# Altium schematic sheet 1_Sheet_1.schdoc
size 599 x 426 mm; Name: A_A2; Symbol: A_A2; Device: A_A2; @Project Name: HydromatMK1_2025-12-27_13-47-41; REV: 1.0; Date: 2025-12-12; Sheet: 1/1; Company: Your Company; Convert to PCB: yes; Add into BOM: yes; spicePre: .; @Page No: 1; @Page Count: 1; @Schematic Name: HydromatMK1; @Board Name: HydromatMK1; @Update Date: 2026-03-11; @Create Time: 13:47:52; @Update Time: 00:05:39; @Page Name: Sheet_1; @Create Date: 2025-12-27
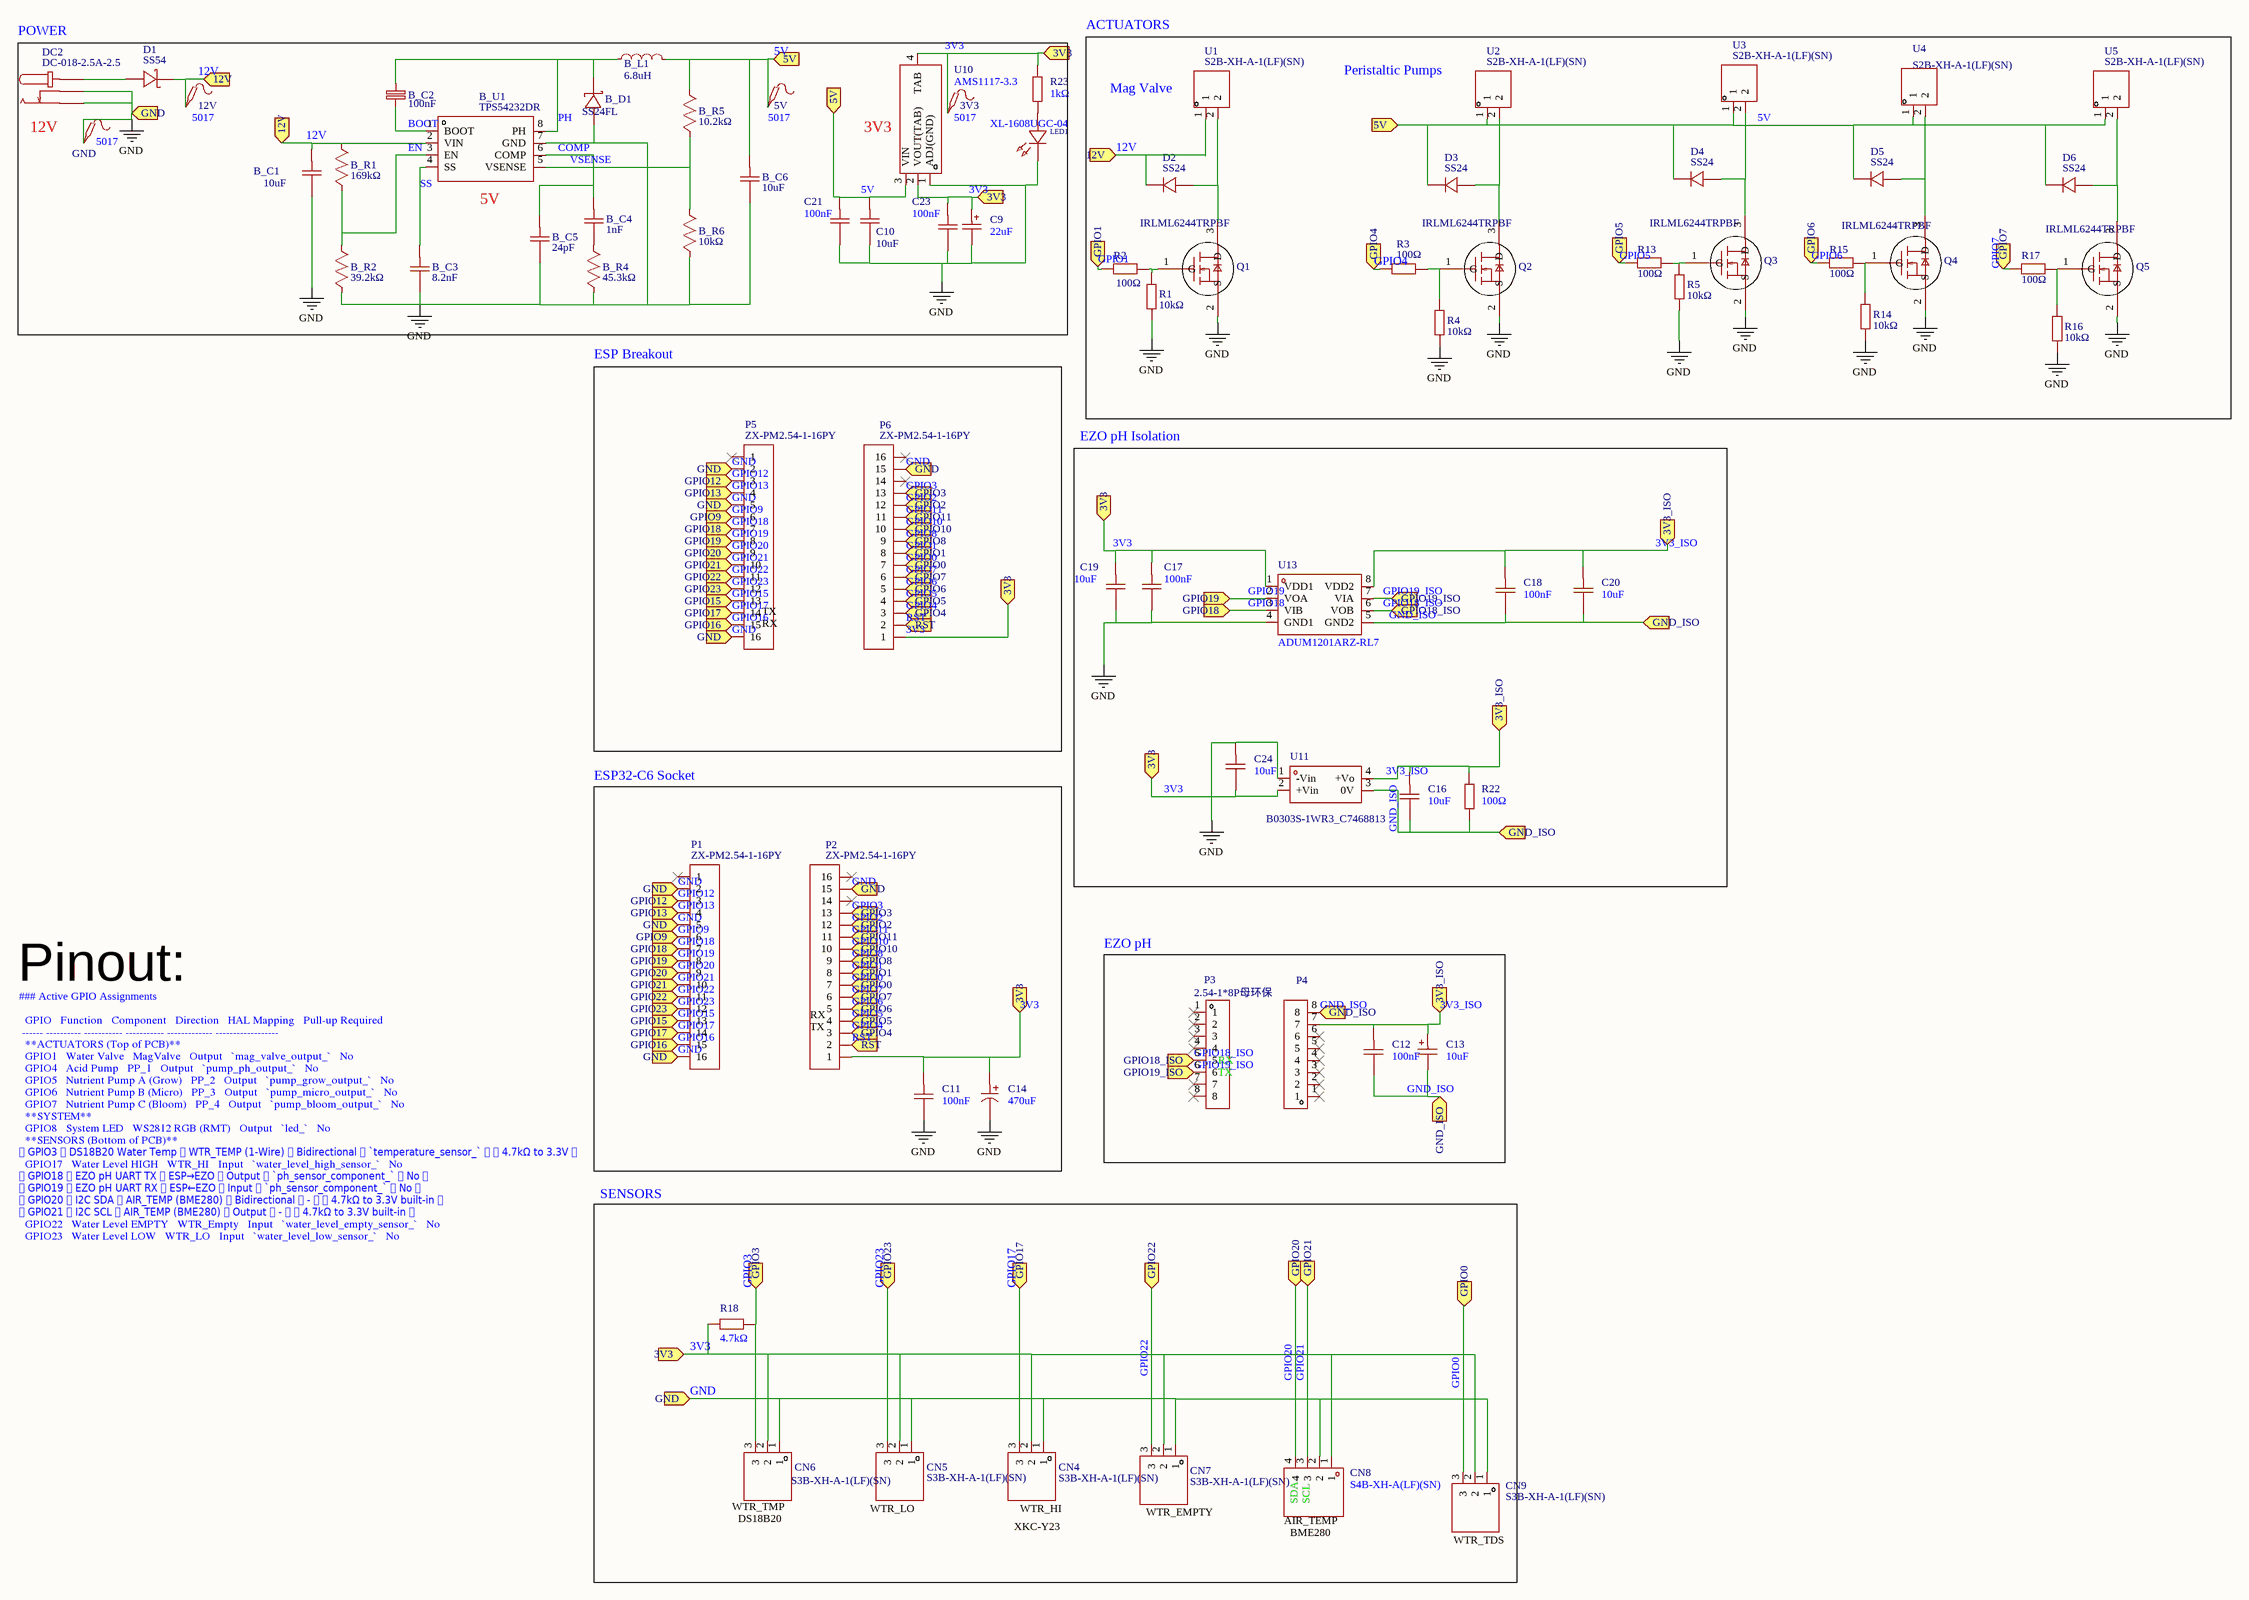
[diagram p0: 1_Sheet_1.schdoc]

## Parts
3V3  5017  [TEST-SMD_L2.7-W1.0]
5V  5017  [TEST-SMD_L2.7-W1.0]
12V  5017  [TEST-SMD_L2.7-W1.0]
B_C1  10uF  [C0603]
B_C2  100nF  [C0603]
B_C3  8.2nF  [C0805]
B_C4  1nF  [C0805]
B_C5  24pF  [C0805]
B_C6  10uF  [C0805]
B_D1  SS24FL  [SOD-123_L2.6-W1.6-LS3.5-RD]
B_L1  6.8uH  [IND-SMD_L2.5-W2.0_FTC252010S]
B_R1  169kΩ  [R0603]
B_R2  39.2kΩ  [R0603]
B_R4  45.3kΩ  [R0805]
B_R5  10.2kΩ  [R0805]
B_R6  10kΩ  [R0805]
B_U1  TPS54232DR  [SOIC-8_L4.9-W3.9-P1.27-LS6.0-BL]
C9  22uF  [CASE-B_3528]
C10  10uF  [C0805]
C11  100nF  [C0805]
C12  100nF  [C0805]
C13  10uF  [CAP-SMD_L3.2-W1.6-RD-C7171]
C14  470uF  [CAP-SMD_BD10.0-L10.3-W10.3-LS11.0-FD]
C16  10uF  [C0805]
C17  100nF  [C0805]
C18  100nF  [C0805]
C19  10uF  [C0805]
C20  10uF  [C0805]
C21  100nF  [C0805]
C23  100nF  [C0805]
C24  10uF  [C0805]
CN4  S3B-XH-A-1(LF)(SN)  [CONN-TH_S3B-XH-A-1-LF-SN]
CN5  S3B-XH-A-1(LF)(SN)  [CONN-TH_S3B-XH-A-1-LF-SN]
CN6  S3B-XH-A-1(LF)(SN)  [CONN-TH_S3B-XH-A-1-LF-SN]
CN7  S3B-XH-A-1(LF)(SN)  [CONN-TH_S3B-XH-A-1-LF-SN]
CN8  S4B-XH-A(LF)(SN)  [CONN-TH_S4B-XH-A-LF-SN]
CN9  S3B-XH-A-1(LF)(SN)  [CONN-TH_S3B-XH-A-1-LF-SN]
D1  SS54  [SMA_L4.3-W2.6-LS5.1-RD]
D2  SS24  [SMA_L4.3-W2.6-LS5.0-FD]
D3  SS24  [SMA_L4.3-W2.6-LS5.0-FD]
D4  SS24  [SMA_L4.3-W2.6-LS5.0-FD]
D5  SS24  [SMA_L4.3-W2.6-LS5.0-FD]
D6  SS24  [SMA_L4.3-W2.6-LS5.0-FD]
DC2  DC-018-2.5A-2.5  [DC-IN-TH_DC-018]
GND  5017  [TEST-SMD_L2.7-W1.0]
LED1  XL-1608UGC-04  [LED0603-RD_GREEN]
P1  ZX-PM2.54-1-16PY  [HDR-TH_16P-P2.54-V-F-1]
P2  ZX-PM2.54-1-16PY  [HDR-TH_16P-P2.54-V-F-1]
P3  2.54-1*8P母环保  [HDR-TH_8P-P2.54-V-F_2]
P4  2.54-1*8P母环保  [HDR-TH_8P-P2.54-V-F_2]  (value not drawn)
P5  ZX-PM2.54-1-16PY  [HDR-TH_16P-P2.54-V-F-1]
P6  ZX-PM2.54-1-16PY  [HDR-TH_16P-P2.54-V-F-1]
Q1  IRLML6244TRPBF  [SOT-23-3_L2.9-W1.3-P1.90-LS2.4-BR]
Q2  IRLML6244TRPBF  [SOT-23-3_L2.9-W1.3-P1.90-LS2.4-BR]
Q3  IRLML6244TRPBF  [SOT-23-3_L2.9-W1.3-P1.90-LS2.4-BR]
Q4  IRLML6244TRPBF  [SOT-23-3_L2.9-W1.3-P1.90-LS2.4-BR]
Q5  IRLML6244TRPBF  [SOT-23-3_L2.9-W1.3-P1.90-LS2.4-BR]
R1  10kΩ  [R0805]
R2  100Ω  [R0805]
R3  100Ω  [R0805]
R4  10kΩ  [R0805]
R5  10kΩ  [R0805]
R13  100Ω  [R0805]
R14  10kΩ  [R0805]
R15  100Ω  [R0805]
R16  10kΩ  [R0805]
R17  100Ω  [R0805]
R18  4.7kΩ  [R0805]
R22  100Ω  [R0805]
R23  1kΩ  [R0805]
U1  S2B-XH-A-1(LF)(SN)  [CONN-TH_S2B-XH-A-1-LF-SN]
U2  S2B-XH-A-1(LF)(SN)  [CONN-TH_S2B-XH-A-1-LF-SN]
U3  S2B-XH-A-1(LF)(SN)  [CONN-TH_S2B-XH-A-1-LF-SN]
U4  S2B-XH-A-1(LF)(SN)  [CONN-TH_S2B-XH-A-1-LF-SN]
U5  S2B-XH-A-1(LF)(SN)  [CONN-TH_S2B-XH-A-1-LF-SN]
U10  AMS1117-3.3  [SOT-223-4_L6.5-W3.5-P2.30-LS7.0-BR]
U11  220kHz  [PWRM-TH_B0303S-1WR3]  (value not drawn)
U13  ADUM1201ARZ-RL7  [SOIC-8_L4.9-W3.9-P1.27-LS6.0-BL]

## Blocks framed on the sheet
ESP Breakout: P5 P6
EZO pH Isolation: C16-C20 C24 R22 U11 U13
ESP32-C6 Socket: C11 C14 P1 P2
EZO pH: C12 C13 P3 P4
SENSORS: CN4-CN9 R18

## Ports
3V3 (in), 3V3_ISO (in), 5V (in), 12V (in), GND (in), GND_ISO (in), GPIO0 (in), GPIO1 (in), GPIO2 (in), GPIO3 (in), GPIO4 (in), GPIO5 (in), GPIO6 (in), GPIO7 (in), GPIO8 (in), GPIO9 (in), GPIO10 (in), GPIO11 (in), GPIO12 (in), GPIO13 (in), GPIO15 (in), GPIO16 (in), GPIO17 (in), GPIO18 (in), GPIO18_ISO (in), GPIO19 (in), GPIO19_ISO (in), GPIO20 (in), GPIO21 (in), GPIO22 (in), GPIO23 (in), RST (in)

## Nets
GND: B_C1.1 B_C3.1 B_C5.1 B_C6.1 B_D1.2(A) B_R2.1 B_R4.1 B_R6.1 B_U1.7(GND) C9.2 C10.1 C11.1 C14.2 C17.1 C19.1 C21.1 C23.1 C24.2 CN4.1 CN5.1 CN6.1 CN7.1 CN8.2 CN9.1 DC2.2 DC2.3 GND.1 LED1.1(K) P1.2 P1.5 P1.16 P2.15 P5.2 P5.5 P5.16 P6.15 Q1.2(S) Q2.2(S) Q3.2(S) Q4.2(S) Q5.2(S) R1.1 R4.1 R5.1 R14.1 R16.1 U10.1(ADJ(GND)) U11.1(-Vin) U13.4(GND1) ; port GND
3V3: 3V3.1 C9.1 C11.2 C14.1 C17.2 C19.2 C23.2 C24.1 CN4.2 CN5.2 CN6.2 CN7.2 CN8.1 CN9.2 P2.1 P6.1 R18.1 R23.2 U10.2(VOUT(TAB)) U10.4(TAB) U11.2(+Vin) U13.1(VDD1) ; port 3V3
3V3_ISO: C12.2 C13.1 C16.2 C18.2 C20.2 P4.7 R22.2 U11.4(+Vo) U13.8(VDD2) ; port 3V3_ISO
5V: 5V.1 B_C6.2 B_L1.2 B_R5.2 C10.2 C21.2 D3.1(C) D4.1(C) D5.1(C) D6.1(C) U2.1 U3.1 U4.1 U5.1 U10.3(VIN) ; port 5V
12V: 12V.1 B_C1.2 B_R1.2 B_U1.2(VIN) D1.1(K) D2.1(C) U1.1 ; port 12V
BOOT: B_C2.2 B_U1.1(BOOT)
COMP: B_C4.2 B_C5.2 B_U1.6(COMP)
EN: B_R1.1 B_R2.2 B_U1.3(EN)
GND_ISO: C12.1 C13.2 C16.1 C18.1 C20.1 P4.8 R22.1 U11.3(0V) U13.5(GND2) ; port GND_ISO
GPIO0: CN9.3 P2.7 P6.7 ; port GPIO0
GPIO1: P2.8 P6.8 R2.1 ; port GPIO1
GPIO2: P2.12 P6.12 ; port GPIO2
GPIO3: CN6.3 P2.13 P6.13 R18.2 ; port GPIO3
GPIO4: P2.3 P6.3 R3.2 ; port GPIO4
GPIO5: P2.4 P6.4 R13.2 ; port GPIO5
GPIO6: P2.5 P6.5 R15.2 ; port GPIO6
GPIO7: P2.6 P6.6 R17.1 ; port GPIO7
GPIO8: P2.9 P6.9 ; port GPIO8
GPIO9: P1.6 P5.6 ; port GPIO9
GPIO10: P2.10 P6.10 ; port GPIO10
GPIO11: P2.11 P6.11 ; port GPIO11
GPIO12: P1.3 P5.3 ; port GPIO12
GPIO13: P1.4 P5.4 ; port GPIO13
GPIO15: P1.13 P5.13 ; port GPIO15
GPIO16: P1.15 P5.15 ; port GPIO16
GPIO17: CN4.3 P1.14 P5.14 ; port GPIO17
GPIO18: P1.7 P5.7 U13.3(VIB) ; port GPIO18
GPIO18_ISO: P3.5 U13.6(VOB) ; port GPIO18_ISO
GPIO19: P1.8 P5.8 U13.2(VOA) ; port GPIO19
GPIO19_ISO: P3.6 U13.7(VIA) ; port GPIO19_ISO
GPIO20: CN8.4 P1.9 P5.9 ; port GPIO20
GPIO21: CN8.3 P1.10 P5.10 ; port GPIO21
GPIO22: CN7.3 P1.11 P5.11 ; port GPIO22
GPIO23: CN5.3 P1.12 P5.12 ; port GPIO23
PH: B_C2.1 B_D1.1(K) B_L1.1 B_U1.8(PH)
RST: P2.2 P6.2 ; port RST
SS: B_C3.2 B_U1.4(SS)
VSENSE: B_R5.1 B_R6.2 B_U1.5(VSENSE)
NetB_C4_1: B_C4.1 B_R4.2
NetD1_2: D1.2(A) DC2.1
NetD2_2: D2.2(A) Q1.3(D) U1.2
NetD3_2: D3.2(A) Q2.3(D) U2.2
NetD4_2: D4.2(A) Q3.3(D) U3.2
NetD5_2: D5.2(A) Q4.3(D) U4.2
NetD6_2: D6.2(A) Q5.3(D) U5.2
NetLED1_2: LED1.2(A) R23.1
NetQ1_1: Q1.1(G) R1.2 R2.2
NetQ2_1: Q2.1(G) R3.1 R4.2
NetQ3_1: Q3.1(G) R5.2 R13.1
NetQ4_1: Q4.1(G) R14.2 R15.1
NetQ5_1: Q5.1(G) R16.2 R17.2

Not connected (* = marked no-connect by the designer): P1 1*; P2 14* 16*; P3 1* 2* 3* 4* 7* 8*; P4 1* 2* 3* 4* 5* 6*; P5 1*; P6 14* 16*

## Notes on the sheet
- (near DC2) POWER
- ACTUATORS
- (near U1) Mag Valve
- (near U2) Peristaltic Pumps
- (near DC2) 12V
- (near U10) 3V3
- (near B_U1) 5V
- (near P5) TX
- (near P5) RX
- Pinout:
- ### Active GPIO Assignments
   GPIO  Function  Component  Direction  HAL Mapping  Pull-up Required 
  ---------------------------------------------------------------------
   **ACTUATORS (Top of PCB)** 
   GPIO1  Water Valve  MagValve  Output  `mag_valve_output_`  No 
   GPIO4  Acid Pump  PP_1  Output  `pump_ph_output_`  No 
   GPIO5  Nutrient Pump A (Grow)  PP_2  Output  `pump_grow_output_`  No 
   GPIO6  Nutrient Pump B (Micro)  PP_3  Output  `pump_micro_output_`  No 
   GPIO7  Nutrient Pump C (Bloom)  PP_4  Output  `pump_bloom_output_`  No 
   **SYSTEM** 
   GPIO8  System LED  WS2812 RGB (RMT)  Output  `led_`  No 
   **SENSORS (Bottom of PCB)** 
   GPIO3  DS18B20 Water Temp  WTR_TEMP (1-Wire)  Bidirectional  `temperature_sensor_`  ✅ 4.7kΩ to 3.3V 
   GPIO17  Water Level HIGH  WTR_HI  Input  `water_level_high_sensor_`  No 
   GPIO18  EZO pH UART TX  ESP→EZO  Output  `ph_sensor_component_`  No 
   GPIO19  EZO pH UART RX  ESP←EZO  Input  `ph_sensor_component_`  No 
   GPIO20  I2C SDA  AIR_TEMP (BME280)  Bidirectional  -  ✅ 4.7kΩ to 3.3V built-in 
   GPIO21  I2C SCL  AIR_TEMP (BME280)  Output  -  ✅ 4.7kΩ to 3.3V built-in 
   GPIO22  Water Level EMPTY  WTR_Empty  Input  `water_level_empty_sensor_`  No 
   GPIO23  Water Level LOW  WTR_LO  Input  `water_level_low_sensor_`  No 
- (near P2) TX
- (near P2) RX
- (near P3) RX
- (near P3) TX
- WTR_TMP
- DS18B20
- WTR_LO
- XKC-Y23
- WTR_HI
- WTR_EMPTY
- AIR_TEMP
- BME280
- (near CN8) SDA
- (near CN8) SCL
- WTR_TDS

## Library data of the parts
3V3 = 5017_C238130: Manufacturer: Keystone; Symbol: Test-Point; Add into BOM: yes; Connector Type: Ferrite Ring (SMD); Plastic Color: Non-Plastic; Board Space (Diameter φ/ Length x Width): 3.4mmx1.8mm; Channel ID: $1e5103
5V = 5017_C238130: Manufacturer: Keystone; Symbol: Test-Point; Add into BOM: yes; Connector Type: Ferrite Ring (SMD); Plastic Color: Non-Plastic; Board Space (Diameter φ/ Length x Width): 3.4mmx1.8mm; Channel ID: $1e5005
12V = 5017_C238130: Manufacturer: Keystone; Symbol: Test-Point; Add into BOM: yes; Connector Type: Ferrite Ring (SMD); Plastic Color: Non-Plastic; Board Space (Diameter φ/ Length x Width): 3.4mmx1.8mm; Channel ID: $1e5056
B_C1 = CL10A106MO8NQNC: Manufacturer: SAMSUNG(三星); Add into BOM: yes; Tolerance: ±20%; Voltage Rating: 16V; Temperature Coefficient: X5R; Channel ID: $1e1201
B_C2 = CC0603KRX7R9BB104: Manufacturer: YAGEO(国巨); Add into BOM: yes; Tolerance: ±10%; Voltage Rating: 50V; Temperature Coefficient: X7R; Origin Footprint: C0402; Channel ID: $1e1005
B_C3 = CC0805JRX7R9BB822: Manufacturer: YAGEO(国巨); Add into BOM: yes; Tolerance: ±5%; Voltage Rating: 50V; Temperature Coefficient: X7R; Origin Footprint: C0201; nameAlias: Value(F); Contributor: LCEDA_Lib; Channel ID: $1e1053
B_C4 = CL21B102KBCNNNC: Manufacturer: SAMSUNG(三星); Add into BOM: yes; Tolerance: ±10%; Voltage Rating: 50V; Temperature Coefficient: X7R; Channel ID: $1e1165
B_C5 = 0805CG240J500NT: Manufacturer: FH(风华); Add into BOM: yes; Tolerance: ±5%; Voltage Rating: 50V; Temperature Coefficient: C0G; Channel ID: $1e1147
B_C6 = CL21A106KBYQNNE: Manufacturer: SAMSUNG(三星); Add into BOM: yes; Tolerance: ±10%; Voltage Rating: 50V; Temperature Coefficient: X5R; Origin Footprint: C1206; nameAlias: Value(F); Contributor: LCEDA_Lib; Channel ID: $1e1093
B_D1 = SS24FL: Manufacturer: KEXIN(科信); Symbol: SS24FL_C489144; Add into BOM: yes; Voltage - Forward(Vf@If): 550mV@2A; Voltage - DC Reverse(Vr): 40V; Current - Rectified: 2A; Non-Repetitive Peak Forward Surge Current: 50A; Contributor: LCSC; Channel ID: $1e1222
B_L1 = FTC252012S6R8MBCA: Manufacturer: cjiang(长江微电); Add into BOM: yes; Tolerance: ±20%; Current Rating: 1.6A; Current - Saturation(Isat): 2A; DC Resistance(DCR): 245mΩ; Origin Footprint: L0805; nameAlias: Value(H); Contributor: LCEDA_Lib; Channel ID: $1e1075
B_R1 = 0603WAF1693T5E: Manufacturer: UNI-ROYAL(厚声); Symbol: 169K; Add into BOM: yes; Tolerance: ±1%; Temperature Coefficient: ±100ppm/℃; Origin Footprint: R0402; nameAlias: Value(Ω); Contributor: LCEDA_Lib; Channel ID: $1e1017; Voltage-Supply(Max): 50V
B_R2 = 0603WAF3922T5E: Manufacturer: UNI-ROYAL(厚声); Symbol: 39K2; Add into BOM: yes; Tolerance: ±1%; Power(Watts): 100mW; Voltage-Supply(Max): 75V; Temperature Coefficient: ±100ppm/℃; Origin Footprint: R0402; nameAlias: Value(Ω); Contributor: LCEDA_Lib; Channel ID: $1e1035
B_R4 = FRC0805F4532TS: Manufacturer: FOJAN(富捷); Symbol: 45K3; Add into BOM: yes; Tolerance: ±1%; Power(Watts): 125mW; Voltage-Supply(Max): 150V; Temperature Coefficient: ±100ppm/℃; Origin Footprint: R0402; nameAlias: Value(Ω); Contributor: LCEDA_Lib; Channel ID: $1e1183
B_R5 = FRC0805F1022TS: Manufacturer: FOJAN(富捷); Symbol: 10K2; Add into BOM: yes; Tolerance: ±1%; Power(Watts): 125mW; Voltage-Supply(Max): 150V; Temperature Coefficient: ±100ppm/℃; Origin Footprint: R0402; nameAlias: Value(Ω); Contributor: LCEDA_Lib; Channel ID: $1e1111
B_R6 = FRC0805J103TS: Manufacturer: FOJAN(富捷); Symbol: 1K87; Add into BOM: yes; Tolerance: ±5%; Power(Watts): 125mW; Voltage-Supply(Max): 150V; Temperature Coefficient: ±100ppm/℃; Channel ID: $1e1129
B_U1 = TPS54232DR: Manufacturer: TI(德州仪器); Add into BOM: yes; Function: Step-down type; Output Type: Adjustable; Input Voltage: 3.5V~28V; Output Voltage: 800mV~28V; Output Current: 2A; Switching Frequency: 1MHz; Synchronous Rectification: No; Number of Outputs: 1; Topology: Step-down; Switch tube (built-in/external): Built-in; Contributor: LCSC; Channel ID: $1e983
C9 = TAJB226K016RNJ: Manufacturer: Kyocera AVX; Add into BOM: yes; Tolerance: ±10%; Voltage Rating: 16V; Equivalent Series Resistance(ESR): 2.3Ω@100kHz
C10 = 10uF: Manufacturer Part: CL21A106KAYNNNE; Manufacturer: SAMSUNG(三星); Convert to PCB: yes; nameAlias: Value
C11 = CC0805KRX7R9BB104: Manufacturer: YAGEO(国巨); Symbol: CC0603KRX7R9BB104; Add into BOM: yes; Tolerance: ±10%; Voltage Rating: 50V; Temperature Coefficient: X7R; Channel ID: $1e4020
C12 = CC0805KRX7R9BB104: Manufacturer: YAGEO(国巨); Symbol: CC0603KRX7R9BB104; Add into BOM: yes; Tolerance: ±10%; Voltage Rating: 50V; Temperature Coefficient: X7R; Channel ID: $1e4054
C13 = TAJA106K016RNJ: Manufacturer: Kyocera AVX; Add into BOM: yes; Tolerance: ±10%; Voltage Rating: 16V; Equivalent Series Resistance(ESR): 3Ω@100kHz
C14 = RVT1E471M1010: Manufacturer: HONOR(荣誉); Symbol: RVT1C471M0607; Add into BOM: yes; Tolerance: ±20%; Lifetime @ Temp: 2000hrs@105℃; Voltage Rating: 35V; Channel ID: $1e4226
C16 C19 C20 C24 = GRM21BR71A106KE51L: Manufacturer: muRata(村田); Add into BOM: yes; Tolerance: ±10%
C17 = CC0805KRX7R9BB104: Manufacturer: YAGEO(国巨); Symbol: CC0603KRX7R9BB104; Add into BOM: yes; Tolerance: ±10%; Voltage Rating: 50V; Temperature Coefficient: X7R; Channel ID: $1e8929
C18 = CC0805KRX7R9BB104: Manufacturer: YAGEO(国巨); Symbol: CC0603KRX7R9BB104; Add into BOM: yes; Tolerance: ±10%; Voltage Rating: 50V; Temperature Coefficient: X7R; Channel ID: $1e8963
C21 = CC0805KRX7R9BB104: Manufacturer: YAGEO(国巨); Symbol: CC0603KRX7R9BB104; Add into BOM: yes; Tolerance: ±10%; Voltage Rating: 50V; Temperature Coefficient: X7R; Channel ID: $1e12932
C23 = CC0805KRX7R9BB104: Manufacturer: YAGEO(国巨); Symbol: CC0603KRX7R9BB104; Add into BOM: yes; Tolerance: ±10%; Voltage Rating: 50V; Temperature Coefficient: X7R; Channel ID: $1e13045
CN4 = S3B-XH-A-1(LF)(SN): Manufacturer: JST; Symbol: S3B-XH-A (LF)(SN); Add into BOM: yes; Pins Structure: 1x3P; Pitch: 2.5mm; Reference Series: XH; Number of PINs Per Row: 3; Current Rating: 3A; Voltage Rating: 250V; Plastic Material: PA66; Flame Retardant Rating: UL94V-0; Supplementary Features: K Pin; Z-Height of the Board: 6.1mm; X-Length of Bottom Edge on Board (Spacing Line): 9.9mm; Y-Width of Bottom Edge on Board: 11.5mm; Origin Footprint: CONN-TH_S3B-XH-A-LF-SN; Contributor: LCSC; Channel ID: $1e1415
CN5 = S3B-XH-A-1(LF)(SN): Manufacturer: JST; Symbol: S3B-XH-A (LF)(SN); Add into BOM: yes; Pins Structure: 1x3P; Pitch: 2.5mm; Reference Series: XH; Number of PINs Per Row: 3; Current Rating: 3A; Voltage Rating: 250V; Plastic Material: PA66; Flame Retardant Rating: UL94V-0; Supplementary Features: K Pin; Z-Height of the Board: 6.1mm; X-Length of Bottom Edge on Board (Spacing Line): 9.9mm; Y-Width of Bottom Edge on Board: 11.5mm; Origin Footprint: CONN-TH_S3B-XH-A-LF-SN; Contributor: LCSC; Channel ID: $1e1433
CN6 = S3B-XH-A-1(LF)(SN): Manufacturer: JST; Symbol: S3B-XH-A (LF)(SN); Add into BOM: yes; Pins Structure: 1x3P; Pitch: 2.5mm; Reference Series: XH; Number of PINs Per Row: 3; Current Rating: 3A; Voltage Rating: 250V; Plastic Material: PA66; Flame Retardant Rating: UL94V-0; Supplementary Features: K Pin; Z-Height of the Board: 6.1mm; X-Length of Bottom Edge on Board (Spacing Line): 9.9mm; Y-Width of Bottom Edge on Board: 11.5mm; Origin Footprint: CONN-TH_S3B-XH-A-LF-SN; Contributor: LCSC; Channel ID: $1e1451
CN7 CN9 = S3B-XH-A-1(LF)(SN): Manufacturer: JST; Symbol: S3B-XH-A (LF)(SN); Add into BOM: yes; Pins Structure: 1x3P; Pitch: 2.5mm; Reference Series: XH; Number of PINs Per Row: 3; Current Rating: 3A; Voltage Rating: 250V; Plastic Material: PA66; Flame Retardant Rating: UL94V-0; Supplementary Features: K Pin; Z-Height of the Board: 6.1mm; X-Length of Bottom Edge on Board (Spacing Line): 9.9mm; Y-Width of Bottom Edge on Board: 11.5mm; Origin Footprint: CONN-TH_S3B-XH-A-LF-SN; Contributor: LCSC; Channel ID: $1e3939
CN8 = S4B-XH-A(LF)(SN): Manufacturer: JST; Add into BOM: yes; Pins Structure: 1x4P; Pitch: 2.5mm; Reference Series: XH; Number of PINs Per Row: 4; Current Rating: 3A; Voltage Rating: 250V; Plastic Material: PA66; Flame Retardant Rating: UL94V-0; Supplementary Features: K Pin; Z-Height of the Board: 6.1mm; X-Length of Bottom Edge on Board (Spacing Line): 12.4mm; Y-Width of Bottom Edge on Board: 11.5mm
D1 = SS54_C20609300: Manufacturer: JSMSEMI(杰盛微); Symbol: MBRS140T3G; Add into BOM: yes; Voltage - Forward(Vf@If): 550mV@5A; Voltage - DC Reverse(Vr): 40V; Current - Rectified: 5A; Reverse Leakage Current (Ir): 100uA@40V; Operating Junction Temperature Range: -55℃~+150℃; Non-Repetitive Peak Forward Surge Current: 100A; Origin Footprint: SMB_L4.6-W3.6-LS5.3-RD; Contributor: LCSC; Channel ID: $1e156
D2 = SS24_C7420362: Manufacturer: R+O(宏嘉诚); Symbol: 1N4148W-7-F; Add into BOM: yes; Diode Configuration: Independent; Voltage - Forward(Vf@If): 550mV@2A; Voltage - DC Reverse(Vr): 40V; Current - Rectified: 2A; Reverse Leakage Current (Ir): 200uA@40V; Operating Junction Temperature Range: -55℃~+150℃; Non-Repetitive Peak Forward Surge Current: 50A; Origin Footprint: SOD-123_L2.7-W1.6-LS3.7-RD-1; Channel ID: $1e228
D3 = SS24_C7420362: Manufacturer: R+O(宏嘉诚); Symbol: 1N4148W-7-F; Add into BOM: yes; Diode Configuration: Independent; Voltage - Forward(Vf@If): 550mV@2A; Voltage - DC Reverse(Vr): 40V; Current - Rectified: 2A; Reverse Leakage Current (Ir): 200uA@40V; Operating Junction Temperature Range: -55℃~+150℃; Non-Repetitive Peak Forward Surge Current: 50A; Origin Footprint: SOD-123_L2.7-W1.6-LS3.7-RD-1; Channel ID: $1e611
D4 = SS24_C7420362: Manufacturer: R+O(宏嘉诚); Symbol: 1N4148W-7-F; Add into BOM: yes; Diode Configuration: Independent; Voltage - Forward(Vf@If): 550mV@2A; Voltage - DC Reverse(Vr): 40V; Current - Rectified: 2A; Reverse Leakage Current (Ir): 200uA@40V; Operating Junction Temperature Range: -55℃~+150℃; Non-Repetitive Peak Forward Surge Current: 50A; Origin Footprint: SOD-123_L2.7-W1.6-LS3.7-RD-1; Channel ID: $1e736
D5 = SS24_C7420362: Manufacturer: R+O(宏嘉诚); Symbol: 1N4148W-7-F; Add into BOM: yes; Diode Configuration: Independent; Voltage - Forward(Vf@If): 550mV@2A; Voltage - DC Reverse(Vr): 40V; Current - Rectified: 2A; Reverse Leakage Current (Ir): 200uA@40V; Operating Junction Temperature Range: -55℃~+150℃; Non-Repetitive Peak Forward Surge Current: 50A; Origin Footprint: SOD-123_L2.7-W1.6-LS3.7-RD-1; Channel ID: $1e833
D6 = SS24_C7420362: Manufacturer: R+O(宏嘉诚); Symbol: 1N4148W-7-F; Add into BOM: yes; Diode Configuration: Independent; Voltage - Forward(Vf@If): 550mV@2A; Voltage - DC Reverse(Vr): 40V; Current - Rectified: 2A; Reverse Leakage Current (Ir): 200uA@40V; Operating Junction Temperature Range: -55℃~+150℃; Non-Repetitive Peak Forward Surge Current: 50A; Origin Footprint: SOD-123_L2.7-W1.6-LS3.7-RD-1; Channel ID: $1e930
DC2 = DC-018-2.5A-2.5: Manufacturer: XKB Connection(中国星坤); Convert to PCB: yes; Contributor: lcsc
GND = 5017_C238130: Manufacturer: Keystone; Symbol: Test-Point; Add into BOM: yes; Connector Type: Ferrite Ring (SMD); Plastic Color: Non-Plastic; Board Space (Diameter φ/ Length x Width): 3.4mmx1.8mm; Channel ID: $1e6615
LED1 = XL-1608UGC-04: Manufacturer: XINGLIGHT(成兴光); Add into BOM: yes; Illumination Color: Emerald Green; Voltage - Forward(Vf): 3.3V; Power(Watts): 70mW; Forward Current: 20mA; Wavelength - Dominant: 515nm~535nm; Peak Wavelength: 525nm; Diode Configuration: Discrete Diode; Lens Color: Water Clear; Luminous Intensity: 810mcd; Viewing Angle: 120°
P1 = ZX-PM2.54-1-16PY: Manufacturer: Megastar(兆星); Symbol: Header-Female-2.54_1x16; Add into BOM: yes; Holes Structure: 1x16P; Pitch: 2.54mm; Circular Hole / Square Hole: Square Hole; Number of Positions: 16P; Current Rating: 3A; Holes Direction: Top; PIN Length: 3.2mm; Channel ID: $1e329
P2 = ZX-PM2.54-1-16PY: Manufacturer: Megastar(兆星); Symbol: Header-Female-2.54_1x16; Add into BOM: yes; Holes Structure: 1x16P; Pitch: 2.54mm; Circular Hole / Square Hole: Square Hole; Number of Positions: 16P; Current Rating: 3A; Holes Direction: Top; PIN Length: 3.2mm; Channel ID: $1e105
P3 = 2.54-1*8P母环保: Manufacturer: BOOMELE(博穆精密); Symbol: Header-Female-2.54_1x8; Add into BOM: yes; Holes Structure: 1x8P; Pitch: 2.54mm; Circular Hole / Square Hole: Square Hole; Number of Positions: 8P; Current Rating: 3A; Holes Direction: Top; PIN Length: 3.2mm; Channel ID: $1e122
P4 = 2.54-1*8P母环保: Manufacturer: BOOMELE(博穆精密); Symbol: Header-Female-2.54_1x8; Add into BOM: yes; Holes Structure: 1x8P; Pitch: 2.54mm; Circular Hole / Square Hole: Square Hole; Number of Positions: 8P; Current Rating: 3A; Holes Direction: Top; PIN Length: 3.2mm; Channel ID: $1e139
P5 = ZX-PM2.54-1-16PY: Manufacturer: Megastar(兆星); Symbol: Header-Female-2.54_1x16; Add into BOM: yes; Holes Structure: 1x16P; Pitch: 2.54mm; Circular Hole / Square Hole: Square Hole; Number of Positions: 16P; Current Rating: 3A; Holes Direction: Top; PIN Length: 3.2mm; Channel ID: $1e1246
P6 = ZX-PM2.54-1-16PY: Manufacturer: Megastar(兆星); Symbol: Header-Female-2.54_1x16; Add into BOM: yes; Holes Structure: 1x16P; Pitch: 2.54mm; Circular Hole / Square Hole: Square Hole; Number of Positions: 16P; Current Rating: 3A; Holes Direction: Top; PIN Length: 3.2mm; Channel ID: $1e1350
Q1 = IRLML6244TRPBF: Manufacturer: Infineon(英飞凌); Symbol: IRLML6244TRPBF_C5123965; Add into BOM: yes; Number: 1 N-Channel; Drain to Source Voltage: 20V; Current - Continuous Drain(Id): 6.3A; RDS(on): 27mΩ@2.5V,5.1A; Pd - Power Dissipation: 1.3W; Gate Threshold Voltage (Vgs(th)): 1.1V@10uA; Gate Charge(Qg): 8.9nC@4.5V; Input Capacitance(Ciss): 700pF; Reverse Transfer Capacitance (Crss@Vds): 98pF; Output Capacitance(Coss): 140pF; Contributor: lcsc; Channel ID: $1e174
Q2 = IRLML6244TRPBF: Manufacturer: Infineon(英飞凌); Symbol: IRLML6244TRPBF_C5123965; Add into BOM: yes; Number: 1 N-Channel; Drain to Source Voltage: 20V; Current - Continuous Drain(Id): 6.3A; RDS(on): 27mΩ@2.5V,5.1A; Pd - Power Dissipation: 1.3W; Gate Threshold Voltage (Vgs(th)): 1.1V@10uA; Gate Charge(Qg): 8.9nC@4.5V; Input Capacitance(Ciss): 700pF; Reverse Transfer Capacitance (Crss@Vds): 98pF; Output Capacitance(Coss): 140pF; Contributor: lcsc; Channel ID: $1e664
Q3 = IRLML6244TRPBF: Manufacturer: Infineon(英飞凌); Symbol: IRLML6244TRPBF_C5123965; Add into BOM: yes; Number: 1 N-Channel; Drain to Source Voltage: 20V; Current - Continuous Drain(Id): 6.3A; RDS(on): 27mΩ@2.5V,5.1A; Pd - Power Dissipation: 1.3W; Gate Threshold Voltage (Vgs(th)): 1.1V@10uA; Gate Charge(Qg): 8.9nC@4.5V; Input Capacitance(Ciss): 700pF; Reverse Transfer Capacitance (Crss@Vds): 98pF; Output Capacitance(Coss): 140pF; Contributor: lcsc; Channel ID: $1e682
Q4 = IRLML6244TRPBF: Manufacturer: Infineon(英飞凌); Symbol: IRLML6244TRPBF_C5123965; Add into BOM: yes; Number: 1 N-Channel; Drain to Source Voltage: 20V; Current - Continuous Drain(Id): 6.3A; RDS(on): 27mΩ@2.5V,5.1A; Pd - Power Dissipation: 1.3W; Gate Threshold Voltage (Vgs(th)): 1.1V@10uA; Gate Charge(Qg): 8.9nC@4.5V; Input Capacitance(Ciss): 700pF; Reverse Transfer Capacitance (Crss@Vds): 98pF; Output Capacitance(Coss): 140pF; Contributor: lcsc; Channel ID: $1e779
Q5 = IRLML6244TRPBF: Manufacturer: Infineon(英飞凌); Symbol: IRLML6244TRPBF_C5123965; Add into BOM: yes; Number: 1 N-Channel; Drain to Source Voltage: 20V; Current - Continuous Drain(Id): 6.3A; RDS(on): 27mΩ@2.5V,5.1A; Pd - Power Dissipation: 1.3W; Gate Threshold Voltage (Vgs(th)): 1.1V@10uA; Gate Charge(Qg): 8.9nC@4.5V; Input Capacitance(Ciss): 700pF; Reverse Transfer Capacitance (Crss@Vds): 98pF; Output Capacitance(Coss): 140pF; Contributor: lcsc; Channel ID: $1e876
R1 = 0805W8F1002T5E: Manufacturer: UNI-ROYAL(厚声); Add into BOM: yes; Tolerance: ±1%; Power(Watts): 125mW; Voltage-Supply(Max): 150V; Temperature Coefficient: ±100ppm/℃; nameAlias: Value; Channel ID: $1e192
R2 = 0805W8F1000T5E_C17408: Manufacturer: UNI-ROYAL(厚声); Symbol: 33Ω; Add into BOM: yes; Tolerance: ±1%; Temperature Coefficient: ±100ppm/℃; Voltage-Supply(Max): 150V; Channel ID: $1e567
R3 = 0805W8F1000T5E_C17408: Manufacturer: UNI-ROYAL(厚声); Symbol: 33Ω; Add into BOM: yes; Tolerance: ±1%; Temperature Coefficient: ±100ppm/℃; Voltage-Supply(Max): 150V; Channel ID: $1e585
R4 = 0805W8F1002T5E: Manufacturer: UNI-ROYAL(厚声); Add into BOM: yes; Tolerance: ±1%; Power(Watts): 125mW; Voltage-Supply(Max): 150V; Temperature Coefficient: ±100ppm/℃; nameAlias: Value; Channel ID: $1e646
R5 = 0805W8F1002T5E: Manufacturer: UNI-ROYAL(厚声); Add into BOM: yes; Tolerance: ±1%; Power(Watts): 125mW; Voltage-Supply(Max): 150V; Temperature Coefficient: ±100ppm/℃; nameAlias: Value; Channel ID: $1e700
R13 = 0805W8F1000T5E_C17408: Manufacturer: UNI-ROYAL(厚声); Symbol: 33Ω; Add into BOM: yes; Tolerance: ±1%; Temperature Coefficient: ±100ppm/℃; Voltage-Supply(Max): 150V; Channel ID: $1e761
R14 = 0805W8F1002T5E: Manufacturer: UNI-ROYAL(厚声); Add into BOM: yes; Tolerance: ±1%; Power(Watts): 125mW; Voltage-Supply(Max): 150V; Temperature Coefficient: ±100ppm/℃; nameAlias: Value; Channel ID: $1e797
R15 = 0805W8F1000T5E_C17408: Manufacturer: UNI-ROYAL(厚声); Symbol: 33Ω; Add into BOM: yes; Tolerance: ±1%; Temperature Coefficient: ±100ppm/℃; Voltage-Supply(Max): 150V; Channel ID: $1e858
R16 = 0805W8F1002T5E: Manufacturer: UNI-ROYAL(厚声); Add into BOM: yes; Tolerance: ±1%; Power(Watts): 125mW; Voltage-Supply(Max): 150V; Temperature Coefficient: ±100ppm/℃; nameAlias: Value; Channel ID: $1e894
R17 = 0805W8F1000T5E_C17408: Manufacturer: UNI-ROYAL(厚声); Symbol: 33Ω; Add into BOM: yes; Tolerance: ±1%; Temperature Coefficient: ±100ppm/℃; Voltage-Supply(Max): 150V; Channel ID: $1e955
R18 = 0805W8F4701T5E: Manufacturer: UNI-ROYAL(厚声); Symbol: RC0603FR-074K7L; Add into BOM: yes; Tolerance: ±1%; Temperature Coefficient: ±100ppm/℃; Voltage-Supply(Max): 75V; Channel ID: $1e3199
R22 = 0805W8F1000T5E_C17408: Manufacturer: UNI-ROYAL(厚声); Symbol: 0603WAF1000T5E; Add into BOM: yes; Tolerance: ±1%; Temperature Coefficient: ±100ppm/℃; Channel ID: $1e9158
R23 = FRC0805J102 TS: Manufacturer: FOJAN(富捷); Symbol: 0603WAF1001T5E; Add into BOM: yes; Tolerance: ±5%; Power(Watts): 125mW; Voltage-Supply(Max): 150V; Temperature Coefficient: ±100ppm/℃; Channel ID: $1e9464
U1 = S2B-XH-A-1(LF)(SN): Manufacturer: JST; Symbol: S2B-XH-A-(LF)(SN); Add into BOM: yes; Pins Structure: 1x2P; Pitch: 2.5mm; Reference Series: XH; Number of PINs Per Row: 2; Current Rating: 3A; Voltage Rating: 250V; Plastic Material: PA66; Flame Retardant Rating: UL94V-0; Supplementary Features: K Pin; Z-Height of the Board: 6.1mm; X-Length of Bottom Edge on Board (Spacing Line): 7.4mm; Y-Width of Bottom Edge on Board: 11.5mm; Origin Footprint: CONN-TH_S2B-XH-A-LF-SN; Contributor: LCSC; Channel ID: $1e210
U2 = S2B-XH-A-1(LF)(SN): Manufacturer: JST; Symbol: S2B-XH-A-(LF)(SN); Add into BOM: yes; Pins Structure: 1x2P; Pitch: 2.5mm; Reference Series: XH; Number of PINs Per Row: 2; Current Rating: 3A; Voltage Rating: 250V; Plastic Material: PA66; Flame Retardant Rating: UL94V-0; Supplementary Features: K Pin; Z-Height of the Board: 6.1mm; X-Length of Bottom Edge on Board (Spacing Line): 7.4mm; Y-Width of Bottom Edge on Board: 11.5mm; Origin Footprint: CONN-TH_S2B-XH-A-LF-SN; Contributor: LCSC; Channel ID: $1e628
U3 = S2B-XH-A-1(LF)(SN): Manufacturer: JST; Symbol: S2B-XH-A-(LF)(SN); Add into BOM: yes; Pins Structure: 1x2P; Pitch: 2.5mm; Reference Series: XH; Number of PINs Per Row: 2; Current Rating: 3A; Voltage Rating: 250V; Plastic Material: PA66; Flame Retardant Rating: UL94V-0; Supplementary Features: K Pin; Z-Height of the Board: 6.1mm; X-Length of Bottom Edge on Board (Spacing Line): 7.4mm; Y-Width of Bottom Edge on Board: 11.5mm; Origin Footprint: CONN-TH_S2B-XH-A-LF-SN; Contributor: LCSC; Channel ID: $1e718
U4 = S2B-XH-A-1(LF)(SN): Manufacturer: JST; Symbol: S2B-XH-A-(LF)(SN); Add into BOM: yes; Pins Structure: 1x2P; Pitch: 2.5mm; Reference Series: XH; Number of PINs Per Row: 2; Current Rating: 3A; Voltage Rating: 250V; Plastic Material: PA66; Flame Retardant Rating: UL94V-0; Supplementary Features: K Pin; Z-Height of the Board: 6.1mm; X-Length of Bottom Edge on Board (Spacing Line): 7.4mm; Y-Width of Bottom Edge on Board: 11.5mm; Origin Footprint: CONN-TH_S2B-XH-A-LF-SN; Contributor: LCSC; Channel ID: $1e815
U5 = S2B-XH-A-1(LF)(SN): Manufacturer: JST; Symbol: S2B-XH-A-(LF)(SN); Add into BOM: yes; Pins Structure: 1x2P; Pitch: 2.5mm; Reference Series: XH; Number of PINs Per Row: 2; Current Rating: 3A; Voltage Rating: 250V; Plastic Material: PA66; Flame Retardant Rating: UL94V-0; Supplementary Features: K Pin; Z-Height of the Board: 6.1mm; X-Length of Bottom Edge on Board (Spacing Line): 7.4mm; Y-Width of Bottom Edge on Board: 11.5mm; Origin Footprint: CONN-TH_S2B-XH-A-LF-SN; Contributor: LCSC; Channel ID: $1e912
U10 = AMS1117-3.3_C347222: Manufacturer: UMW(友台半导体); Add into BOM: yes; Output Type: Fixed; Voltage - Supply: 12V; Output Voltage: 3.3V; Output Current: 1A; Power Supply Rejection Ratio (PSRR): 60dB@(120Hz); Voltage Dropout: 1.3V@(1A); standby current: 5mA; Noise: 0.003%Vout; Output Configuration: Positive; Number of Outputs: 1
U11 = B0303S-1WR3_C7468813: Manufacturer: YLPTEC(易川); Add into BOM: yes; Number of Channels: 1; Output Power: 1W; Voltage - Supply: 2.97V~3.63V; Conversion Efficiency: 81%; Output Voltage: 3.3V; Output Current(Max): 303mA; Capacitive Load(Max): 2400uF; Isolation Voltage(Vrms): 1.5kV; No-Load Input Current: 10mA; Ripple Noise: 30mVp-p
U13 = ADUM1201ARZ-RL7: Manufacturer: ADI(亚德诺); Add into BOM: yes; Number of Forward Channels: 1; Data Rate(Max): 1Mbps; Isolation Voltage(Vrms): 2500; CMTI(kV/us): 25kV/us; Voltage - Supply(VCCA): 2.7V~5.5V; Propagation Delay(tpd): 50ns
